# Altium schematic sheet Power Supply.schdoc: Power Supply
size A4; Organization: Altium Limited; Address1: L3, 12a Rodborough Rd; Address2: Frenchs Forest; Address3: NSW; Address4: Australia 2086; DocumentNumber: 1; SheetNumber: 1; SheetTotal: 1
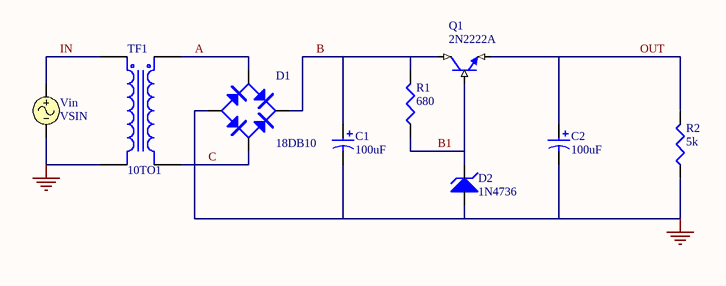
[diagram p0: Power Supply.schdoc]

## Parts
C1  100uF
C2  100uF
D1  18DB10
D2  1N4736
Q1  2N2222A
R1  680
R2  5k
TF1  10TO1
Vin  VSIN

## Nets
GND: C1.2 C2.2 D1.1(V-) D2.1(A) R2.2(BOT) TF1.2(Pri-) Vin.2
A: D1.2(AC) TF1.3(Sec+)
B: C1.1 D1.3(V+) Q1.1(C) R1.1(TOP)
B1: D2.2(K) Q1.2(B) R1.2(BOT)
C: D1.4(AC) TF1.4(Sec-)
IN: TF1.1(Pri+) Vin.1
OUT: C2.1 Q1.3(E) R2.1(TOP)

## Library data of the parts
C1 C2 = CAP2: Bi-Polar Capacitor
D1 = 18DB10: Diode Bridge
D2 = 1N4736: Zener Diode
Q1 = 2N2222A: NPN BJT
R1 R2 = RES: Resistor
TF1 = 10TO1: Transformer
Vin = VSIN: Sinusoidal Voltage Source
